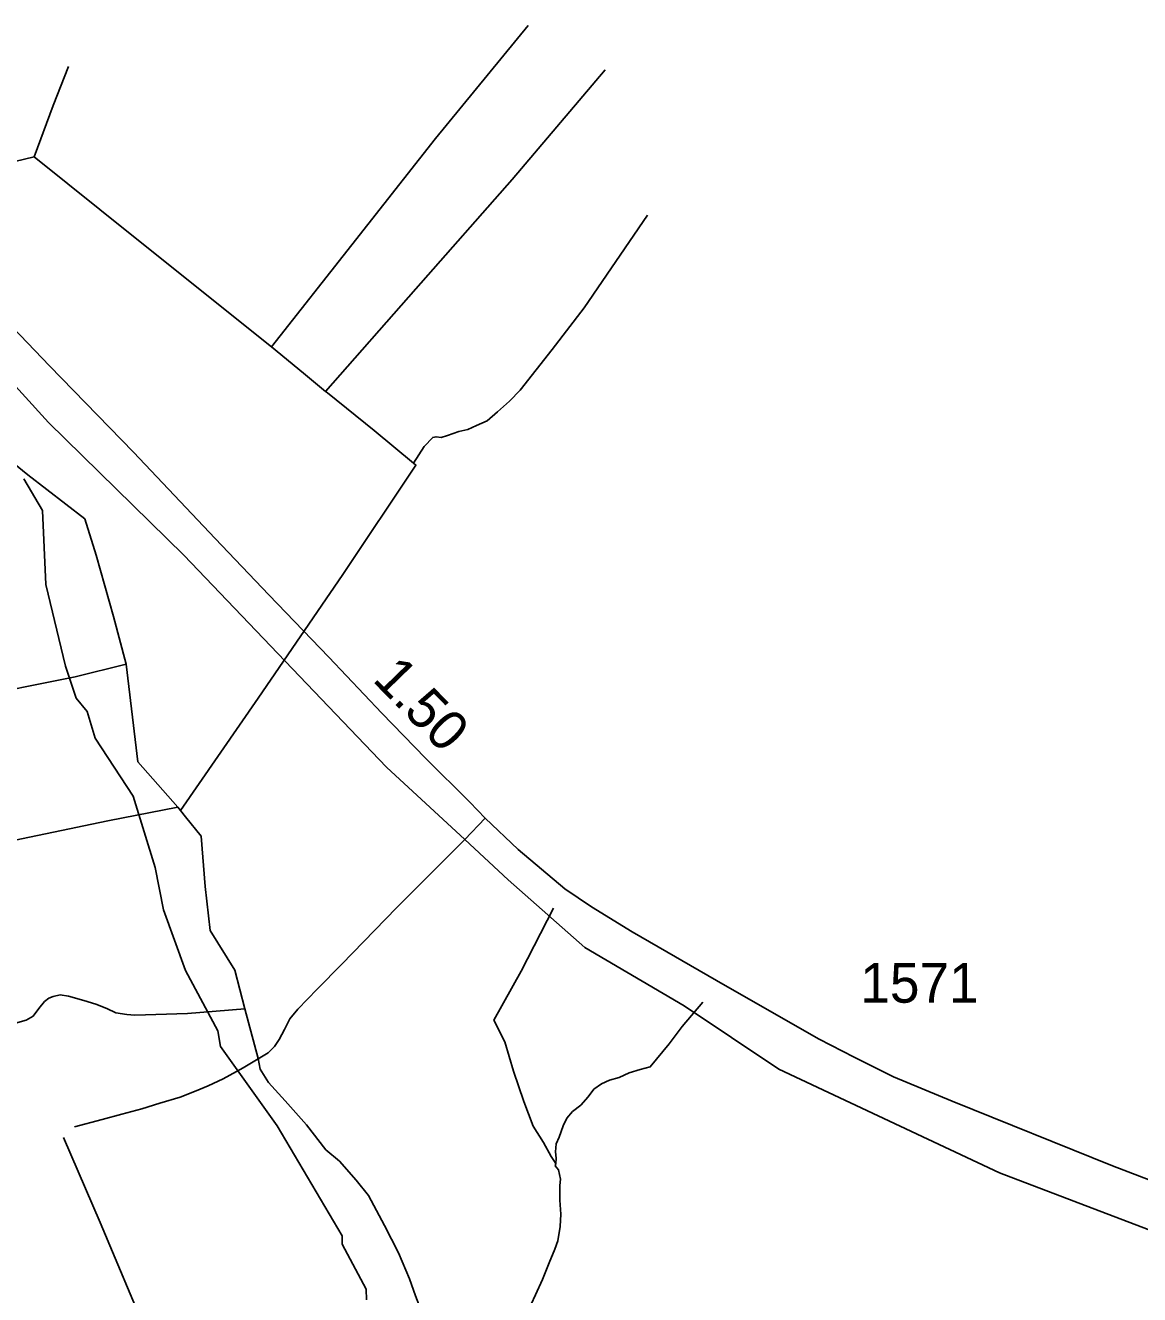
# Model space of a CAD drawing. Extents: x 2315291 to 2336543, y 597177 to 615230.
# Drawn here: x 2321792 to 2325292, y 602063 to 606051 of the extents above; entities that cross this region are included whole.
import ezdxf

# ---------------------------------------------------------------- set-up
doc = ezdxf.new("R2010")
doc.units = 0
for name, color, linetype in [('Exist Boundary Political Urban Extension UEB', 7, 'Continuous'), ('Exist Hydrographic Creek Single Shore', 7, 'Continuous'), ('Exist Hydrographic Misc Water Feature', 7, 'Continuous'), ('Exist Road Non-System Type 51', 7, 'Continuous'), ('Exist Road Secondary Mileage Hundredths English Label', 7, 'Continuous'), ('Exist Road Secondary Type 51 Attributed', 7, 'Continuous'), ('Exist Road Secondary Type 51 Number Label', 7, 'Continuous')]:
    doc.layers.add(name, color=color, linetype=linetype)

msp = doc.modelspace()

# ---------------------------------------------------------------- linework, layer by layer
at = {"layer": 'Exist Boundary Political Urban Extension UEB'}
for points in [[(2321015.6, 605736.9), (2321439.6, 605270.6), (2321864.3, 604803.4), (2322289.1, 604385.8), (2322926.3, 603720.4), (2323172.1, 603492.9)], [(2323172.1, 603492.9), (2323308.6, 603366.5), (2323549.3, 603154.1), (2323860.8, 602970.1), (2324158.2, 602771.8), (2324852, 602446.2), (2325574.1, 602170.2), (2326183, 601929.5), (2326377, 601842)]]:
    msp.add_lwpolyline(points, dxfattribs=at)
at = {"layer": 'Exist Hydrographic Creek Single Shore'}
msp.add_lwpolyline([(2322863.2, 602047.3), (2322862.4, 602080.1), (2322786.3, 602221.4), (2322786.3, 602247.7), (2322582.3, 602593.8), (2322404.3, 602842.6), (2322396.3, 602891.5), (2322294.4, 603081), (2322225.3, 603271.8), (2322199.3, 603405.3), (2322130.4, 603628.9), (2322011.2, 603811.2), (2321985.4, 603895.5), (2321951.4, 603936.8), (2321917.3, 604037.1), (2321856.2, 604293.9), (2321845.3, 604526.5), (2321786.3, 604625.7)], dxfattribs=at)
at = {"layer": 'Exist Hydrographic Misc Water Feature'}
for p, q in [((2321391.8, 605533.6), (2321819.7, 605637.9)), ((2322270.6, 603594.2), (2322278.6, 603584.1))]:
    msp.add_line(p, q, dxfattribs=at)
for points in [[(2323371.5, 606050.7), (2323079.5, 605695.6), (2322817.5, 605361.2), (2322564.9, 605040.7)], [(2321927.6, 605921.3), (2321879.2, 605798.9), (2321819.7, 605637.9)], [(2323612.9, 605911.4), (2323320.7, 605566.5), (2323018.4, 605223.5), (2322734.4, 604900.4)], [(2321819.7, 605637.9), (2322131.2, 605387.8), (2322564.9, 605040.7)], [(2320706.5, 605522.3), (2321168.1, 605157.7), (2321601.7, 604798.4), (2321799.6, 604638.4), (2321978.8, 604500.3), (2322013.9, 604386.8), (2322068, 604193.7), (2322107.8, 604044.1)], [(2323746, 605455), (2323546.9, 605163), (2323446.6, 605032.1), (2323345.9, 604904.9), (2323312.1, 604870.6), (2323274.6, 604836.2), (2323242.6, 604808.1), (2323209.1, 604793.7), (2323181.3, 604781.3), (2323153.4, 604774.9), (2323117.3, 604762.5), (2323097.6, 604756.5), (2323081.8, 604758.1), (2323071.6, 604756), (2323043.9, 604727.7), (2323010.7, 604675.5)], [(2322564.9, 605040.7), (2322665.8, 604957.8), (2322734.4, 604900.4)], [(2322734.4, 604900.4), (2322740.6, 604896.7), (2322887, 604778.1), (2323010.7, 604675.5)], [(2323010.7, 604675.5), (2323018.4, 604669.5), (2322788.4, 604325.3), (2322522.6, 603936.7), (2322278.6, 603584.1)], [(2320128.8, 604418.6), (2320178.5, 604247.3), (2320211.5, 604143.8), (2320238.6, 604035.9), (2320259.7, 603950.4), (2320266, 603884.5), (2320268.5, 603838.3), (2320281.4, 603782.9), (2320299.9, 603733.1), (2320535.1, 603787.3), (2320886.3, 603873.1), (2320896.4, 603861.1), (2320904.6, 603839.2), (2320917.1, 603801.6), (2321270.2, 603865.3), (2321603, 603934.8), (2321948.3, 604004.5), (2322107.8, 604044.1)], [(2322107.8, 604044.1), (2322145.1, 603736.8), (2322270.6, 603594.2)], [(2321057.3, 603355.5), (2321512.5, 603439.8), (2322051, 603551.8), (2322270.6, 603594.2)], [(2322278.6, 603584.1), (2322294.8, 603564.2), (2322343.4, 603503), (2322356.9, 603345.2), (2322372.3, 603207.5), (2322449.6, 603082.3), (2322481, 602960.8)], [(2323451.1, 603277.1), (2323349.4, 603079.9), (2323262.9, 602925), (2323297.7, 602857.7), (2323324.8, 602765.6), (2323357.8, 602670.2), (2323386.5, 602592.5), (2323419.1, 602541), (2323443.3, 602497.2), (2323458.1, 602475.5)], [(2321174, 602743), (2321479.3, 602836.2), (2321793.7, 602925.5), (2321815.8, 602937.6), (2321833.9, 602961.6), (2321851.5, 602983.7), (2321865, 602994.3), (2321879, 603000.3), (2321901.3, 603004.6), (2321927, 603000.8), (2321975.3, 602987.4), (2322013.3, 602975.6), (2322047.1, 602962), (2322075.6, 602948.4), (2322109.9, 602942.8), (2322135.5, 602941), (2322301.4, 602946.8), (2322481, 602960.8)], [(2322481, 602960.8), (2322523, 602805.2), (2322529, 602771.5), (2322555.4, 602729.7), (2322607.9, 602672.4), (2322675, 602597), (2322735.7, 602517.7), (2322778.3, 602482.1), (2322830.8, 602422.7), (2322869.2, 602375.1), (2322920, 602279.9), (2322963.3, 602194.3), (2322998.1, 602112.8), (2323016.8, 602058.9), (2323043.5, 601991.2), (2323065.8, 601929.5), (2323092.9, 601871.9), (2323112.6, 601830), (2323125.3, 601796), (2323147.8, 601760.6), (2323168.1, 601726.7), (2323186.4, 601696.8), (2323206.5, 601669.1)], [(2323920.1, 602982.2), (2323855.1, 602905.6), (2323813.8, 602851), (2323754.6, 602778.4), (2323722.6, 602770.3), (2323688.3, 602759.6), (2323656.8, 602745.3), (2323626.8, 602737.2), (2323601, 602724.9), (2323577.6, 602708.6), (2323559.6, 602684.5), (2323536, 602658), (2323510.2, 602638), (2323492.3, 602617.6), (2323480.6, 602593.7), (2323468.7, 602557.4), (2323458.9, 602537.4), (2323457.3, 602511.3), (2323459.3, 602491.5), (2323458.1, 602475.5)], [(2321911.8, 602556.9), (2322026.8, 602290.2), (2322176.1, 601934), (2322357.1, 601854.1), (2322572.2, 601762), (2322607.5, 601770.5), (2322647.7, 601777.1), (2322679.9, 601771.4), (2322715.8, 601759.9), (2322746.1, 601750.1), (2322764.2, 601738.5), (2322792.5, 601716.8), (2322824.9, 601696.9), (2322850.3, 601679.3), (2322904.6, 601663.8), (2322962.9, 601652.6), (2323031.2, 601637.4), (2323077.1, 601631.7), (2323123, 601626.5), (2323161.4, 601624.8), (2323197, 601623), (2323227, 601615.3)], [(2323458.1, 602475.5), (2323455.8, 602467.3), (2323466.1, 602455.6), (2323472.2, 602425.5), (2323470.6, 602405.5), (2323471, 602359.6), (2323473.5, 602315.8), (2323471.8, 602277.5), (2323464.2, 602231.7), (2323454.8, 602205.5), (2323437, 602163.2), (2323415.6, 602111.2), (2323394.5, 602062.9), (2323380.6, 602033), (2323369.3, 601992.9), (2323349.4, 601950.5), (2323324, 601900.4), (2323302.6, 601858.2), (2323271.1, 601819.9), (2323247.7, 601773.5), (2323233.7, 601735.5), (2323222.1, 601701.1), (2323206.5, 601669.1)]]:
    msp.add_lwpolyline(points, dxfattribs=at)
at = {"layer": 'Exist Road Non-System Type 51'}
msp.add_line((2323172.1, 603492.9), (2323236.3, 603560), dxfattribs=at)
msp.add_lwpolyline([(2321945.9, 602590), (2322032.6, 602613.3), (2322094.3, 602630), (2322157.7, 602646.7), (2322214.3, 602665), (2322277.7, 602683.4), (2322327.7, 602703.4), (2322366, 602719.3), (2322412.7, 602740.9), (2322476.1, 602776), (2322522.8, 602804.3), (2322554.4, 602822.7), (2322574.4, 602842.7), (2322589.4, 602864.4), (2322606.1, 602896.1), (2322622.8, 602929.4), (2322647.8, 602959.5), (2322707.8, 603022.9), (2322786.2, 603101.3), (2322957.9, 603278.1), (2323162.9, 603483.3), (2323172.1, 603492.9)], dxfattribs=at)
at = {"layer": 'Exist Road Secondary Type 51 Attributed'}
msp.add_lwpolyline([(2321565.8, 605295.7), (2321867.6, 604981.3), (2322131, 604709.4), (2322387.7, 604438.3), (2322556.1, 604261.5), (2322744.5, 604066.3), (2322911.2, 603889.5), (2323048.4, 603748.3), (2323187.7, 603609.9), (2323236.3, 603560), (2323339.3, 603461.6), (2323486.3, 603338.1), (2323569.7, 603281.4), (2323698.1, 603203), (2323989.8, 603034.5), (2324284.9, 602866.1), (2324394.9, 602809.3), (2324518.3, 602747.6), (2324703.3, 602670.9), (2325206.8, 602468.2), (2325701.9, 602278)], dxfattribs=at)

# ---------------------------------------------------------------- texts
at = {"layer": 'Exist Road Secondary Mileage Hundredths English Label'}
msp.add_text('1.50', height=125, rotation=314.1731, dxfattribs=at).set_placement((2322879, 603993.2))
at = {"layer": 'Exist Road Secondary Type 51 Number Label'}
msp.add_text('1571', height=125, dxfattribs=at).set_placement((2324414.4, 602980.3))

doc.saveas('drawing.dxf')
